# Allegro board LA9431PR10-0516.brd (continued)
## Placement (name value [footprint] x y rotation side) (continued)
UC2  -  [74AHC1G09GW_TSSOP5]  169.77 73.25 0 top
UC3  -  [TC7SH08FU_SSOP5]  173.34 58.08 90 top
UC4  -  [74AUP1G07GW_TSSOP5]  108.44 96.51 270 top
UC6  -  [74CBTLV3126BQ_DHVQFN14_2P5X3]  75.86 74.07 0 top
UC7  -  [TC7SH08FU_SSOP5]  70.61 72.93 180 top
Y1  -  [Y_X1E000021042600_4P]  184.16 77.53 270 top
Y3  -  [Y_7V25000034_4P]  260.88 79.62 270 top
Y4  -  [Y_Q13FC1350000_2P]  13.77 12.72 270 top
YC1  -  [Y_Q13FC135000040_2P]  159.67 56.2 180 bottom
YC2  -  [Y_X3G024000DC1H_4P]  139.71 92.96 270 bottom

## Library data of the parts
C1 C3 C5 C6 C9-C15 C17-C20 C22-C24 C27-C29 C34 C42 C43 C50 C54-C57 C59-C64 C66-C68 C76 C85 C87 C93-C95 C97-C99 C103 C105 C106 C108 C109 C113-C115 C119 C120 C123-C127 C129 C130 C135-C137 C139 C141 C142 C144-C148 C150 C152-C168 C170-C179 C181 C183-C186 C188-C194 C198-C204 C206-C210 C212 C214-C219 C222 C226 C227 C229 C231-C239 C241-C246 C248-C250 C252 C255-C261 C269-C279 C281-C283 C285 C287 C289 C291-C316 C319-C322 C329-C334 C337-C347 C349-C365 C367-C380 C382-C384 C386-C394 C396-C404 C406 C407 C409 C411 C412 C414-C419 C422 C425-C430 C432 C433 C440-C443 C445 C447-C449 C451 C455-C457 CC1-CC15 CC22 CC24 CC26 CC27 CC29-CC33 CC35-CC41 CC44-CC46 CC48 CC51-CC54 CC56 CC58-CC61 CC63-CC70 CC74 CC81 CC82 CC90 CC91 CC149 CC450 CD1-CD13 CD23-CD29 CD32-CD44 CD54-CD57 CD60 CD61 CE1 CE2 CE8 CE9 PC3 PC4 PC101 PC105 PC106 PC108 PC202 PC203 PC212-PC215 PC300 PC301 PC305 PC308 PC400 PC402 PC403 PC501-PC504 PC506 PC511-PC514 PC707 PC708 PC719 PC724-PC730 PC740 PC801 PC805 PC806 PC808-PC810 PC812 PC814 PC817 = C_0402
C7 C187 C251 CC47 CE7 PC5 PC10 PC102-PC104 PC107 PC200 PC201 PC205 PC302 PC303 PC401 PC404 PC706 PC711 PC712 PC716-PC718 PC731 PC732 PC734 PC736 PC737 PC741 PC742 PC807 PC900-PC929 = C_0805
C8 C16 C21 C25 C26 C52 C65 C88 C116-C118 C121 C122 C128 C131 C132 C134 C138 C140 C151 C169 C180 C182 C211 C213 C220 C221 C223-C225 C228 C230 C240 C247 C262 C284 C288 C317 C318 C323-C326 C328 C336 C348 C366 C385 C405 C408 C410 C413 C420 C431 C446 C452-C454 C458-C461 CC16-CC21 CC28 CC34 CC42 CC43 CC49 CC50 CC62 CC76 CC77 CD14-CD21 CD30 CD31 CD45-CD52 CD58 CD59 PC1 PC2 PC6-PC9 PC11 PC12 PC100 PC109-PC112 PC114 PC116-PC119 PC204 PC208 PC209 PC211 PC304 PC306 PC500 PC505 PC507-PC510 PC700 PC703-PC705 PC709 PC713-PC715 PC720-PC722 PC733 PC803 PC811 PC813 PC815 PC816 = C_0603
C253 C254 C280 C290 C444 PC307 = C_B2
C327 = C_1808
CC55 CC75 CC78 CC79 = C_1206
CC71-CC73 PC207 = C_D2
CD22 CD53 = C_D3
CMOS1 JTAG1 ME1 = SHORTPADS: User Part Number: PART#
D1 = RB751V40_SC76-2
D2 D10 D21 = BAT54CW_SOT323-3
D8 D16 D18 D33 = L30ESDL5V0C3-2_SOT23-3
D12-D14 D19 D23 D24 = RB751S40T1G_SOD523-2
D15 D17 D34 = TVWDF1004AD0_DFN9
D20 = PESD24VS2UT_SOT23-3
D30-D32 = L03ESDL5V0CC3-2_SOT23-3
D65 = RB751VM-40TE-17_SOD323-2
FD1-FD4 = FIDUCIAL_C40M80
H1-H4 H12 H13 H15-H18 ST2 = H_2P8
H5 = H_2P3
H8-H11 = H_3P4
H14 = H_2P1
JAPS1 = ACES_50506-01841-P01_18P
JDEG1 = ACES_50521-01041-P01_10P-T
JDIMM1 JDIMM2 = FOX_AS0A621-U4R6-7H_204P
JDOCK1 = JAE_WD2F144WB8-DT_144P-T
JEDP1 = ACES_50398-04071-001_40P
JFAN1 JSF1 = ACES_50277-0040N-001_4P-T
JHDMI1 = LCN_AUF05-1922S10-0019_19P-T
JHP1 = SINGA_2SJ3080-003111F_6P-T
JKBTP1 = E-T_6718K-Y16N-01L_16P-T
JLED1 = ACES_50450-0067N-P01_6P-T
JLOM1 = SANTA_130456-341_13P-T
JMDP1 = ACON_MAR2C-20K1800_20P-T
JMEDIA = E-T_6718K-Y06N-01L_6P-T
JMINI1 JMINI2 = LCN_DAN08-52216-0100_52P-T
JMINI3 = LCN_DAN08-52406-0500_52P
JNFC1 = E-T_6718K-Y15N-01L_15P-T
JRTC1 = TYCO_2-1775293-2_2P
JSD1 = ALPS_SCDADA0101_19P_NR-T
JSH1 = E-T_6718K-Y12N-01L_12P-T
JSPK1 = ACES_50209-0040N-001_4P
JTAA1 = ACES_50185-02041-001_20P-T
JUSB1 JUSB2 = SANTA_373070-1_9P-T
JUSB3 = TAITW_PUBAUE-09FLBS1FF4H0_9P-T
JUSH1 = E-T_6718K-Y20N-00L_20P-T
JXDP1 = SAMTE_BSH-030-01-L-D-A_60P
L1 L2 L4 L5 = MURAT_BLM18AG102SN1D_2P
L8 L39 L54 = MURAT_DLW21HN900SQ2L_4P
L9 L11 L12 L14 L15 L17 L18 L20 = DELTA_0402HS-9N0EJTS_2P
L10 L13 L16 L19 = MURAT_DLW21SN900HQ2L-0805_4P-S
L21 = CHILI_PBY160808T-600Y-N_2P
L22-L25 = MURAT_BLM18PG330SN1D_2P
L26 = TAIYO_CBC2012T4R7M_2P
L27-L34 = DELTA_0603CS-120EJTS_2P
L35 L36 = MURAT_BLM15AG601SN1D_2P
L37 L38 = MURAT_DLW21SN670HQ2L_4P
L40 L41 L55 L56 = MURAT_DLW21SN900HQ2L-0805_4P
L42 = CHENG_OCE2012120YZF_4P
L43 L46-L48 = MURAT_DLW21SN900SQ2L-0805_4P-S
L51 L52 = MURAT_BLM18AG221SN1D_2P
LC1-LC6 = MURAT_LQM2MPN2R2NG0L_2P
LE1 = MURAT_BLM15BB221SN1D_2P
LED1 LED5 LED6 = LED_LTW-193ZDS5_2P
LED7 = LED_LTW-295DSKS-5A_4P
PBATT1 = ALLTO_C144LS-109A9-L_9P-T
PC113 PC115 = C_V
PC735 PC738 = C_D
PD1 PD2 = TVNST52302AB0_SOT523-3
PD3 = BAS40-05W_SC70-3
PD4 PD702 = RB751V-40_SOD323-2
PD5 = DA204U_SOT323-3
PD6 = D_0603
PD701 PD815 = RB717F_SOT323-3
PD800 PD806 PD808 = PDS5100H-13_POWERDI5-3
PD807 PD810 PD811 PD813 PD814 PD816 PD818-PD821 = SDMK0340L-7-F_SOD323-2
PH500 PH501 PR1 PR2 PR7-PR15 PR17 PR18 PR100-PR102 PR104-PR107 PR114 PR201 PR204-PR207 PR209 PR211 PR300 PR302 PR303 PR305 PR307 PR308 PR400-PR403 PR500-PR516 PR521 PR523 PR527-PR529 PR535 PR537 PR540 PR703-PR707 PR711 PR713 PR714 PR722 PR726 PR727 PR729 PR730 PR732 PR734-PR740 PR742-PR744 PR746-PR749 PR751 PR801 PR802 PR804 PR807 PR808 PR810 PR813-PR819 PR822-PR824 PR826-PR830 PR836 PR837 PR839 PR840 PR844 PR846 PR848 PR849 PR851 PR856 PR858 PR864 PR869 PR870 PR874 PR875 PR894 R1-R33 R35 R36 R38-R54 R56-R60 R63-R67 R69 R70 R72 R74 R85 R91 R92 R94-R97 R99 R102 R104 R108 R120-R123 R136 R137 R139 R142 R147-R153 R155-R168 R170-R173 R176 R178 R182 R184-R187 R190 R191 R194 R195 R197 R198 R202 R205-R207 R211-R219 R222 R224-R230 R243 R244 R252-R268 R271-R282 R284 R285 R287-R289 R291-R293 R295 R296 R298-R301 R303-R305 R307 R309-R313 R317 R320-R322 R324-R331 R335 R338-R340 R342-R373 R375-R377 R380-R388 R391-R394 R397-R399 R401-R405 R408 R411 R414 R417 R421 R423 R425 R427-R436 R438-R440 R442 R445 R447 R449-R453 R460 R462-R471 R473-R475 R480 R481 R493 RC1-RC3 RC5-RC12 RC17-RC20 RC22-RC26 RC28 RC30 RC34 RC36-RC39 RC44-RC47 RC50 RC52 RC55-RC58 RC61 RC63 RC64 RC66-RC69 RC71 RC73 RC74 RC76 RC78 RC79 RC81-RC84 RC95 RC96 RC99 RC101-RC106 RC109 RC113-RC120 RC122-RC134 RC136 RC137 RC139-RC141 RC143-RC145 RC147 RC149 RC151-RC155 RC158 RC159 RC161 RC166 RC168-RC170 RC173 RC178 RC180 RC181 RC185 RC189-RC191 RC193 RC195 RC197 RC199-RC206 RC208 RC210 RC211 RC215-RC218 RC221 RC222 RC232 RC233 RC235-RC241 RC243 RC244 RC248-RC250 RC253-RC256 RC258-RC260 RC264-RC266 RC268 RC269 RC272 RC275 RC280 RC282-RC285 RC287-RC289 RC292 RC295 RD3 RE4 RE5 = R_0402
PJP1 PJP101 PJP102 PJP203 PJP204 = JUMP_43X118
PJP4-PJP25 PJP201 PJP202 PJP400-PJP402 PJP701 = JUMP_43X39
PJP100 PJP500 PJP700 = JUMP_43X118-S
PJP200 PJP300 PJP301 = JUMP_43X79
PJPDC1 = ACES_50299-00501-003_5P
PL1 PL2 PL4 = TAIYO_FBMJ4516HS720NT_2P
PL3 = MURAT_BLM15AG102SN1D_2P
PL100 = CYNTE_PCMB053T-1R0MS_2P
PL101 PL102 PL200 PL300 = CYNTE_PCMB064T-3R3MS_2P
PL500 = CYNTE_PDME064T-R36MS1R405_4P
PL501 = L_1812-1806
PL700 = CYNTE_PCMB042T-1R0MS_2P
PL701 = TOKO_FDVE1040-H-3R3M-P3_2P
PQ1 PQ801 PQ814 PQ822 PQ823 PQ829 PQ830 = FDN338P_NL_SOT23-3
PQ2 PQ816 = FDV301N_NL_SOT23-3
PQ3 Q12 = MMST3904-7-F_SOT323-3
PQ4 PQ700 = SI7121DN-T1-GE3_POWERPAK8-5
PQ6 = IMD2AT-108_SC74-6
PQ100-PQ103 PQ200 PQ201 PQ300 PQ301 = SI7326DN-T1-E3_PAK1212-8
PQ701 PQ702 = NTR4502PT1G_SOT23-3
PQ703 = NTGD4161PT1G_TSOP6
PQ704 PQ706 = SIR472DP-T1-GE3_POWERPAK8-5
PQ710 PQ712 PQ802 PQ805-PQ807 PQ812 PQ813 PQ819 PQ821 PQ824 = 2N7002DW-T-R7_SOT363-6
PQ800 PQ809 = SI4835DDY-T1-GE3_SO8
PQ810 PQ811 PQ815 = FDS6679AZ-G_SO8
PQ817 PQ818 PQ825 PQ827 PQ828 PQ831 PQ832 = RHU002N06_SOT323-3
PQ826 = FDMC6679AZ_MLP8-5
PR6 PR103 PR108 PR113 PR208 PR210 PR304 PR520 PR531 PR532 PR534 PR536 PR539 PR701 PR702 PR709 PR710 PR717-PR719 PR725 PR728 PR741 PR750 PR811 PR812 PR820 PR825 PR831-PR834 PR838 PR841 PR843 PR847 PR850 PR852-PR855 PR857 PR859-PR863 PR866 PR868 PR872 PR877 PR895 R37 R73 R75-R77 R81 R84 R88 R106 R107 R129 R131 R143-R145 R154 R169 R174 R175 R177 R179 R180 R183 R193 R196 R220 R223 R231 R241 R242 R269 R270 R297 R306 R315 R319 R332-R334 R336 R337 R341 R374 R378 R379 R400 R410 R413 R416 R418 R420 R422 R424 R426 R441 R443 R444 R472 R490-R492 RC4 RC14 RC29 RC31 RC33 RC35 RC40 RC65 RC72 RC86-RC94 RC97 RC107 RC108 RC110-RC112 RC135 RC142 RC163 RC172 RC174 RC176 RC245-RC247 RC261 RC263 RC267 RC279 RC300 RC301 RD1 RD5-RD7 RD10-RD13 = R0402_0OHM
PR16 PR708 PR835 = R_0805
PR109 PR110 PR200 PR202 PR301 PR517 PR519 PR526 PR715 PR821 RC242 RC276 = R_0603
PR111 PR112 PR203 PR306 PR522 PR724 PR745 = R_1206
PR700 PR716 = R_1206_4P-D
PRP2 RP1-RP11 = RP_0804_8P4R
PU2 = LM393DR_SO8
PU3 PU801 PU804-PU808 U20 U24 U26 U29 U30 U42 U47 UC3 UC7 = TC7SH08FU_SSOP5
PU11 = RT8207MZQW_WQFN20_3X3
PU100 = TPS51225CRUKR_QFN20_3X3
PU111 = TS5A63157DCKR_SC70-6
PU300 = TPS51218DSCR_SON10_3X3
PU400 = APL5915KAI-TRL_SO8
PU500 = TPS51622RSM_QFN32_4X4
PU501 = CSD97374CQ4M_SON8_3P5X4P5-S
PU700 = BQ24715RGRR_QFN20_3P5X3P5
PU703 = INA199A2DCKR_SC70-6
PU800 = CD3301RHHR_QFN36_6X6
Q1 Q3 = LP2301ALT1G_SOT23-3
Q2 = FDC654P-G_SSOT-6
Q4 Q7 Q9 Q29 Q121 = L2N7002WT1G_SC-70-3
Q5 Q17 Q20-Q25 Q28 Q30 Q32 Q33 Q120 Q123 Q124 QC1 = DMN66D0LDW-7_SOT363-6
Q6 Q10 Q31 = BSS138W-7-F_SOT323-3
Q11 Q13 Q14 = MMBT3904WT1G_SC70-3
Q15 Q16 Q26 = PDTA114EU_SC70-3
Q125 = SI3456DDV-T1-GE3_TSOP6
QD1 = BSS138-G_SOT23-3
R100 R101 R235-R240 R246-R251 R482-R487 = R_0402-S
R130 RC262 = R0805_0OHM
R140 R181 RC16 = R0603_0OHM
ST1 = CLIP_C5P1
SW1 = SW_SKRBAAE010_4P
T1-T7 T10-T40 T48-T89 T92 T93 T97 T98 T100 T101 T106 T107 T110 T115 T118 T121-T123 T126 T129-T132 T137-T141 = TPC12
T94 = TAIMA_IH-115-F_24P
U1 = W25Q64FVSSIQ_SO8
U2 = W25Q32FVSSIQ_SO8
U3 U18 U22 U31 U43 U45 U46 = TPS22966DPUR_SON14_2X3
U5 UC4 = 74AUP1G07GW_TSSOP5
U6 = IDTVMM2320BKG8_BGA_168P-NH
U7 = W25X10BVSNIG_SO8
U9 = APL3512ABI-TRG_SOT23-5
U11 U13 U49 = PI3C3125LEX_TSSOP14
U17 = ALC3226-CG_QFN48_7X7
U19 = PI3VDP12412ZHEX_TQFN42_9X3P5
U21 = WGI218LM-QQ89-B0_QFN48_6X6
U23 = PI3L720ZHEX_TQFN42_9X3P5
U25 = AT97SC3204-X2A14-AB_TSSOP28
U27 = OZ777FJ2LN_QFN48_6X6
U32 U35 U52 = G547I2P81U_MSOP8
U33 = PI3USB3102ZLEX_TQFN32_6X3
U36 = NX3DV221GM_XQFN10U10_2X1P55
U37 = ECE5048-LZY_DQFN132_11X11
U38 = MEC5075-LZY_DQFN132_11X11
U39 = SLG55594AVTR_TDFN8_2X2
U41 = RT9818A-44GU3_SC70-3
U48 U50 = AP2330W-7_SC59-3
UC1 = HASWELL-MCP-E-ULT_BGA_1168P-T
UC2 = 74AHC1G09GW_TSSOP5
UC6 = 74CBTLV3126BQ_DHVQFN14_2P5X3
Y1 = Y_X1E000021042600_4P
Y3 = Y_7V25000034_4P
Y4 = Y_Q13FC1350000_2P
YC1 = Y_Q13FC135000040_2P
YC2 = Y_X3G024000DC1H_4P

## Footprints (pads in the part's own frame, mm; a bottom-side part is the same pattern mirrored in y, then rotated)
2N7002DW-T-R7_SOT363-6
  oval 0.381x1.397 smd: 1(0,0) 2(0.65,0) 3(1.3,0) 4(1.3,1.725) 5(0.65,1.725) 6(0,1.725)
74AHC1G09GW_TSSOP5
  oval 0.381x1.346 smd: 1(0,0) 2(0.65,0) 3(1.3,0) 4(1.3,1.79) 5(0,1.79)
74AUP1G07GW_TSSOP5
  oval 0.381x1.346 smd: 1(0,0) 2(0.65,0) 3(1.3,0) 4(1.3,1.79) 5(0,1.79)
74CBTLV3126BQ_DHVQFN14_2P5X3
  oval 1.041x0.254 smd: 1(0,0) 7(2.95,0) 8(2.95,0.5) 14(0,0.5)
  oval 0.254x1.041 smd: 2(0.475,-0.975) 3(0.975,-0.975) 4(1.475,-0.975) 5(1.975,-0.975) 6(2.475,-0.975) 9(2.475,1.475) 10(1.975,1.475) 11(1.475,1.475) 12(0.975,1.475) 13(0.475,1.475)
  rect 1.499x0.991 smd: 15(1.475,0.25)
ACES_50185-02041-001_20P-T
  round 0.787 hole 0.787 unplated: (0.2,-1.315) (3.4,-1.315)
  oval 0.203x0.889 smd: 1(0,0) 2(0,-2.63) 3(0.4,0) 4(0.4,-2.63) 5(0.8,0) 6(0.8,-2.63) 7(1.2,0) 8(1.2,-2.63) 9(1.6,0) 10(1.6,-2.63) 11(2,0) 12(2,-2.63) 13(2.4,0) 14(2.4,-2.63) 15(2.8,0) 16(2.8,-2.63) 17(3.2,0) 18(3.2,-2.63) 19(3.6,0) 20(3.6,-2.63)
  rect 0.508x0.838 smd: 21(-0.8,-0.575) 22(-0.8,-2.055) 23(4.4,-0.575) 24(4.4,-2.055)
ACES_50209-0040N-001_4P
  oval 0.508x1.651 smd: 1(0,0) 2(0.8,0) 3(1.6,0) 4(2.4,0)
  rect 1.194x1.702 smd: 5(-1.3,-2.275) 6(3.7,-2.275)
ACES_50277-0040N-001_4P-T
  oval 0.787x1.905 smd: 1(0,0) 2(1.25,0) 3(2.5,0) 4(3.75,0)
  rect 1.295x3.353 smd: 5(-2.85,-4.925) 6(6.6,-4.925)
ACES_50299-00501-003_5P
  round 1.803 hole 1.803 unplated: (-0.2,5.2) (8.2,5.2)
  oval 0.889x2.388 smd: 1(0,0) 2(2,0) 3(4,0) 4(6,0) 5(8,0)
ACES_50398-04071-001_40P
  oval 0.254x1.295 smd: 1(0,0) 2(-0.5,0) 3(-1,0) 4(-1.5,0) 5(-2,0) 6(-2.5,0) 7(-3,0) 8(-3.5,0) 9(-4,0) 10(-4.5,0) 11(-5,0) 12(-5.5,0) 13(-6,0) 14(-6.5,0) 15(-7,0) 16(-7.5,0) 17(-8,0) 18(-8.5,0) 19(-9,0) 20(-9.5,0) 21(-10,0) 22(-10.5,0) 23(-11,0) 24(-11.5,0) 25(-12,0) 26(-12.5,0) 27(-13,0) 28(-13.5,0) 29(-14,0) 30(-14.5,0) 31(-15,0) 32(-15.5,0) 33(-16,0) 34(-16.5,0) 35(-17,0) 36(-17.5,0) 37(-18,0) 38(-18.5,0) 39(-19,0) 40(-19.5,0)
  rect 1.194x3.2 smd: 41(-21.9,1.95) 45(2.4,1.95)
  rect 2.311x1.295 smd: 42(-18.65,3.9) 43(-9.75,3.9) 44(-0.85,3.9)
ACES_50450-0067N-P01_6P-T
  oval 0.508x1.295 smd: 1(0,0) 2(0.8,0) 3(1.6,0) 4(2.4,0) 5(3.2,0) 6(4,0)
  rect 1.194x1.702 smd: 7(-1.3,1.3) 8(5.3,1.3)
ACES_50506-01841-P01_18P
  oval 0.305x0.889 smd: 1(0,0) 2(0.5,0) 3(1,0) 4(1.5,0) 5(2,0) 6(2.5,0) 7(3,0) 8(3.5,0) 9(4,0) 10(4.5,0) 11(5,0) 12(5.5,0) 13(6,0) 14(6.5,0) 15(7,0) 16(7.5,0) 17(8,0) 18(8.5,0)
  rect 0.991x2.007 smd: 19(-2.1,-3.05) 20(10.6,-3.05)
ACES_50521-01041-P01_10P-T
  oval 0.305x0.787 smd: 1(0,0) 2(-0.5,0) 3(-1,0) 4(-1.5,0) 5(-2,0) 6(-2.5,0) 7(-3,0) 8(-3.5,0) 9(-4,0) 10(-4.5,0)
  rect 0.406x0.787 smd: 11(-5.5,-2.5) 12(1,-2.5)
ACON_MAR2C-20K1800_20P-T
  round 1.194 hole 1.194 unplated: (-6.95,-0.5) (1.55,-0.5)
  round 0.813 hole 0.508: 1(0,0) 3(-0.6,-1.2) 5(-1.1,0) 7(-1.7,-1.2) 9(-2.2,0) 11(-3.2,0) 13(-3.7,-1.2) 15(-4.3,0) 17(-4.8,-1.2) 19(-5.4,0)
  oval 0.406x1.88 smd: 2(0,-2.995) 4(-0.6,-2.995) 6(-1.2,-2.995) 8(-1.8,-2.995) 10(-2.4,-2.995) 12(-3,-2.995) 14(-3.6,-2.995) 16(-4.2,-2.995) 18(-4.8,-2.995) 20(-5.4,-2.995)
  oval 1.194x2.261 hole 0.711x1.753: 21(-8.2,2.96) 22(-8.2,-2.04) 23(2.8,2.96) 24(2.8,-2.04)
ALC3226-CG_QFN48_7X7
  oval 0.254x0.889 smd: 1(0,0) 2(0.5,0) 3(1,0) 4(1.5,0) 5(2,0) 6(2.5,0) 7(3,0) 8(3.5,0) 9(4,0) 10(4.5,0) 11(5,0) 12(5.5,0) 25(5.5,7.1) 26(5,7.1) 27(4.5,7.1) 28(4,7.1) 29(3.5,7.1) 30(3,7.1) 31(2.5,7.1) 32(2,7.1) 33(1.5,7.1) 34(1,7.1) 35(0.5,7.1) 36(0,7.1)
  oval 0.889x0.254 smd: 13(6.3,0.8) 14(6.3,1.3) 15(6.3,1.8) 16(6.3,2.3) 17(6.3,2.8) 18(6.3,3.3) 19(6.3,3.8) 20(6.3,4.3) 21(6.3,4.8) 22(6.3,5.3) 23(6.3,5.8) 24(6.3,6.3) 37(-0.8,6.3) 38(-0.8,5.8) 39(-0.8,5.3) 40(-0.8,4.8) 41(-0.8,4.3) 42(-0.8,3.8) 43(-0.8,3.3) 44(-0.8,2.8) 45(-0.8,2.3) 46(-0.8,1.8) 47(-0.8,1.3) 48(-0.8,0.8)
  rect 5.512x5.512 smd: 49(2.75,3.55)
ALLTO_C144LS-109A9-L_9P-T
  round 1.803 hole 1.194: 1(0,0) 2(2,0) 3(4,0) 4(6,0) 5(8,0) 6(10,0) 7(12,0) 8(14,0) 9(16,0)
  oval 1.6x3.404 hole 0.991x2.794: 10(19.125,0.25) 11(-3.125,0.25)
ALPS_SCDADA0101_19P_NR-T
  round 0.889 hole 0.889 unplated: (-7.075,-28.875) (13.425,-1.775)
  oval 0.787x1.549 smd: 1(0,0) 2(1.4,0) 3(2.8,0) 4(4.2,0) 5(7.1,0) 6(9.9,0) 7(11.3,0) 8(12.7,0) 9(-1.4,0) 18(8.5,0) 19(14.1,0)
  oval 1.346x0.787 smd: 10(-9.2,-22.925) 11(-9.2,-24.025) 12(-9.2,-25.125) 13(-9.2,-26.225) 14(20.05,-26.225) 15(20.05,-25.125) 16(20.05,-24.025) 17(20.05,-22.925)
  rect 1.397x1.448 smd: 20(17.2,0.65) 21(5.65,0.65) 22(-6.35,0.65)
  rect 1.448x1.397 smd: 23(19.525,-6.525) 24(-8.675,-6.525) 25(19.525,-20.625) 26(-8.675,-18.775)
AP2330W-7_SC59-3
  oval 0.787x0.991 smd: 1(0,0) 2(-0.95,-2.4) 3(0.95,-2.4)
APL3512ABI-TRG_SOT23-5
  oval 0.61x1.041 smd: 1(0,0) 2(0.95,0) 3(1.9,0) 4(1.9,2.7) 5(0,2.7)
APL5915KAI-TRL_SO8
  oval 0.635x1.854 smd: 1(0,0) 2(1.27,0) 3(2.54,0) 4(3.81,0) 5(3.81,5.165) 6(2.54,5.165) 7(1.27,5.165) 8(0,5.165)
  rect 2.997x2.591 smd: 9(1.905,2.582)
AT97SC3204-X2A14-AB_TSSOP28
  oval 0.381x1.626 smd: 1(0,0) 2(0.65,0) 3(1.3,0) 4(1.95,0) 5(2.6,0) 6(3.25,0) 7(3.9,0) 8(4.55,0) 9(5.2,0) 10(5.85,0) 11(6.5,0) 12(7.15,0) 13(7.8,0) 14(8.45,0) 15(8.45,5.8) 16(7.8,5.8) 17(7.15,5.8) 18(6.5,5.8) 19(5.85,5.8) 20(5.2,5.8) 21(4.55,5.8) 22(3.9,5.8) 23(3.25,5.8) 24(2.6,5.8) 25(1.95,5.8) 26(1.3,5.8) 27(0.65,5.8) 28(0,5.8)
BAS40-05W_SC70-3
  oval 0.508x0.559 smd: 1(0,0) 2(-0.65,-1.85) 3(0.65,-1.85)
BAT54CW_SOT323-3
  oval 0.66x0.864 smd: 1(0,0) 2(-0.65,-1.85) 3(0.65,-1.85)
BQ24715RGRR_QFN20_3P5X3P5
  oval 0.254x1.041 smd: 1(0,0) 2(0.5,0) 3(1,0) 4(1.5,0) 5(2,0) 11(2,3.45) 12(1.5,3.45) 13(1,3.45) 14(0.5,3.45) 15(0,3.45)
  oval 1.041x0.254 smd: 6(2.725,0.725) 7(2.725,1.225) 8(2.725,1.725) 9(2.725,2.225) 10(2.725,2.725) 16(-0.725,2.725) 17(-0.725,2.225) 18(-0.725,1.725) 19(-0.725,1.225) 20(-0.725,0.725)
  rect 2.057x2.057 smd: 21(1,1.725)
BSS138-G_SOT23-3
  oval 1.016x1.524 smd: 1(0,0) 2(0.965,2.083) 3(-0.965,2.083)
BSS138W-7-F_SOT323-3
  oval 0.711x0.889 smd: 1(0,0) 2(-0.65,-1.9) 3(0.65,-1.9)
C_0402
  rect 0.508x0.559 smd: 1(0,0) 2(0.914,0)
C_0603
  rect 0.635x0.889 smd: 1(0,0) 2(1.397,0)
C_0805
  rect 0.813x1.397 smd: 1(0,0) 2(1.702,0)
C_1206
  rect 1.016x1.651 smd: 1(0,0) 2(2.667,0)
C_1808
  rect 1.041x2.311 smd: 1(0,0) 2(4.35,0)
C_B2
  rect 1.346x2.692 smd: 1(0,0) 2(-2.75,0)
C_D
  rect 2.388x2.896 smd: 1(0,0) 2(6.1,0)
C_D2
  rect 2.388x2.794 smd: 1(0,0) 2(6.4,0)
C_D3
  rect 2.388x2.794 smd: 1(0,0) 2(6.4,0)
C_V
  rect 2.388x2.896 smd: 1(0,0) 2(6.1,0)
CD3301RHHR_QFN36_6X6
  oval 0.254x1.194 smd: 1(0,0) 2(0.5,0) 3(1,0) 4(1.5,0) 5(2,0) 6(2.5,0) 7(3,0) 8(3.5,0) 9(4,0) 19(4,5.8) 20(3.5,5.8) 21(3,5.8) 22(2.5,5.8) 23(2,5.8) 24(1.5,5.8) 25(1,5.8) 26(0.5,5.8) 27(0,5.8)
  oval 1.194x0.254 smd: 10(4.9,0.9) 11(4.9,1.4) 12(4.9,1.9) 13(4.9,2.4) 14(4.9,2.9) 15(4.9,3.4) 16(4.9,3.9) 17(4.9,4.4) 18(4.9,4.9) 28(-0.9,4.9) 29(-0.9,4.4) 30(-0.9,3.9) 31(-0.9,3.4) 32(-0.9,2.9) 33(-0.9,2.4) 34(-0.9,1.9) 35(-0.9,1.4) 36(-0.9,0.9)
  rect 4.089x4.089 smd: 37(2,2.9)
CHENG_OCE2012120YZF_4P
  rect 0.889x0.787 smd: 1(0,0) 2(1.7,0) 3(1.7,1.2) 4(0,1.2)
CHILI_PBY160808T-600Y-N_2P
  rect 0.559x1.041 smd: 1(0,0) 2(1.3,0)
CLIP_C5P1
  round 5.105 smd: 1(0,0)
CSD97374CQ4M_SON8_3P5X4P5-S
  oval 0.203x0.914 smd: 1(0,0) 2(0.4,0) 3(0.8,0) 6(0.8,3.505) 7(0.4,3.505) 8(0,3.505)
  custom 0.225x0.225 smd: 4(2.2,0.265) 5(2.2,3.24)
  rect 4.039x2.21 smd: 9(1.6,1.752)
CYNTE_PCMB042T-1R0MS_2P
  rect 1.499x2.489 smd: 1(0,0) 2(3.7,0)
CYNTE_PCMB053T-1R0MS_2P
  rect 1.905x2.794 smd: 1(0,0) 2(4.1,0)
CYNTE_PCMB064T-3R3MS_2P
  rect 2.362x3.505 smd: 1(0,0) 2(6.05,0)
CYNTE_PDME064T-R36MS1R405_4P
  custom 0.686x0.686 smd: 1(0,0) 4(8.509,0)
  rect 2.362x0.508 smd: 2(1.448,0) 3(7.061,0)
D_0603
  oval 0.864x1.219 smd: 1(-0.711,0) 2(0.711,0)
DA204U_SOT323-3
  oval 0.813x0.914 smd: 1(0,0) 2(0.65,1.6) 3(-0.65,1.6)
DELTA_0402HS-9N0EJTS_2P
  rect 0.508x0.66 smd: 1(0,0) 2(0.96,0)
DELTA_0603CS-120EJTS_2P
  rect 0.635x1.016 smd: 1(0,0) 2(1.28,0)
DMN66D0LDW-7_SOT363-6
  oval 0.432x0.61 smd: 1(0,0) 2(0.65,0) 3(1.3,0) 4(1.3,1.9) 5(0.65,1.9) 6(0,1.9)
E-T_6718K-Y06N-01L_6P-T
  oval 0.305x0.787 smd: 1(0,0) 2(0.5,0) 3(1,0) 4(1.5,0) 5(2,0) 6(2.5,0)
  rect 0.406x0.787 smd: 7(-1,-2.5) 8(3.5,-2.5)
E-T_6718K-Y12N-01L_12P-T
  oval 0.305x0.787 smd: 1(0,0) 2(0.5,0) 3(1,0) 4(1.5,0) 5(2,0) 6(2.5,0) 7(3,0) 8(3.5,0) 9(4,0) 10(4.5,0) 11(5,0) 12(5.5,0)
  rect 0.406x0.787 smd: 13(-1,-2.5) 14(6.5,-2.5)
E-T_6718K-Y15N-01L_15P-T
  oval 0.305x0.787 smd: 1(0,0) 2(0.5,0) 3(1,0) 4(1.5,0) 5(2,0) 6(2.5,0) 7(3,0) 8(3.5,0) 9(4,0) 10(4.5,0) 11(5,0) 12(5.5,0) 13(6,0) 14(6.5,0) 15(7,0)
  rect 0.406x0.787 smd: 16(-1,-2.5) 17(8,-2.5)
E-T_6718K-Y16N-01L_16P-T
  oval 0.305x0.787 smd: 1(0,0) 2(0.5,0) 3(1,0) 4(1.5,0) 5(2,0) 6(2.5,0) 7(3,0) 8(3.5,0) 9(4,0) 10(4.5,0) 11(5,0) 12(5.5,0) 13(6,0) 14(6.5,0) 15(7,0) 16(7.5,0)
  rect 0.406x0.787 smd: 17(-1,-2.5) 18(8.5,-2.5)
E-T_6718K-Y20N-00L_20P-T
  oval 0.305x0.787 smd: 1(0,0) 2(0.5,0) 3(1,0) 4(1.5,0) 5(2,0) 6(2.5,0) 7(3,0) 8(3.5,0) 9(4,0) 10(4.5,0) 11(5,0) 12(5.5,0) 13(6,0) 14(6.5,0) 15(7,0) 16(7.5,0) 17(8,0) 18(8.5,0) 19(9,0) 20(9.5,0)
  rect 0.406x0.787 smd: 21(-1,-2.5) 22(10.5,-2.5)
ECE5048-LZY_DQFN132_11X11
  oval 0.279x0.737 smd: A1(0,0) A2(0.5,0) A3(1,0) A4(1.5,0) A5(2,0) A6(2.5,0) A7(3,0) A8(3.5,0) A9(4,0) A10(4.5,0) A11(5,0) A12(5.5,0) A13(6,0) A14(6.5,0) A15(7,0) A16(7.5,0) A33(7.5,10.9) A34(7,10.9) A35(6.5,10.9) A36(6,10.9) A37(5.5,10.9) A38(5,10.9) A39(4.5,10.9) A40(4,10.9) A41(3.5,10.9) A42(3,10.9) A43(2.5,10.9) A44(2,10.9) A45(1.5,10.9) A46(1,10.9) A47(0.5,10.9) A48(0,10.9)
  oval 0.737x0.279 smd: A17(9.2,1.7) A18(9.2,2.2) A19(9.2,2.7) A20(9.2,3.2) A21(9.2,3.7) A22(9.2,4.2) A23(9.2,4.7) A24(9.2,5.2) A25(9.2,5.7) A26(9.2,6.2) A27(9.2,6.7) A28(9.2,7.2) A29(9.2,7.7) A30(9.2,8.2) A31(9.2,8.7) A32(9.2,9.2) A49(-1.7,9.2) A50(-1.7,8.7) A51(-1.7,8.2) A52(-1.7,7.7) A53(-1.7,7.2) A54(-1.7,6.7) A55(-1.7,6.2) A56(-1.7,5.7) A57(-1.7,5.2) A58(-1.7,4.7) A59(-1.7,4.2) A60(-1.7,3.7) A61(-1.7,3.2) A62(-1.7,2.7) A63(-1.7,2.2) A64(-1.7,1.7)
  oval 0.318x0.61 smd: B1(-0.25,0.855) B2(0.25,0.855) B3(0.75,0.855) B4(1.25,0.855) B5(1.75,0.855) B6(2.25,0.855) B7(2.75,0.855) B8(3.25,0.855) B9(3.75,0.855) B10(4.25,0.855) B11(4.75,0.855) B12(5.25,0.855) B13(5.75,0.855) B14(6.25,0.855) B15(6.75,0.855) B16(7.25,0.855) B17(7.75,0.855) B35(7.75,10.045) B36(7.25,10.045) B37(6.75,10.045) B38(6.25,10.045) B39(5.75,10.045) B40(5.25,10.045) B41(4.75,10.045) B42(4.25,10.045) B43(3.75,10.045) B44(3.25,10.045) B45(2.75,10.045) B46(2.25,10.045) B47(1.75,10.045) B48(1.25,10.045) B49(0.75,10.045) B50(0.25,10.045) B51(-0.25,10.045)
  oval 0.61x0.318 smd: B18(8.345,1.45) B19(8.345,1.95) B20(8.345,2.45) B21(8.345,2.95) B22(8.345,3.45) B23(8.345,3.95) B24(8.345,4.45) B25(8.345,4.95) B26(8.345,5.45) B27(8.345,5.95) B28(8.345,6.45) B29(8.345,6.95) B30(8.345,7.45) B31(8.345,7.95) B32(8.345,8.45) B33(8.345,8.95) B34(8.345,9.45) B52(-0.845,9.45) B53(-0.845,8.95) B54(-0.845,8.45) B55(-0.845,7.95) B56(-0.845,7.45) B57(-0.845,6.95) B58(-0.845,6.45) B59(-0.845,5.95) B60(-0.845,5.45) B61(-0.845,4.95) B62(-0.845,4.45) B63(-0.845,3.95) B64(-0.845,3.45) B65(-0.845,2.95) B66(-0.845,2.45) B67(-0.845,1.95) B68(-0.845,1.45)
  rect 5.105x5.105 smd: C1(3.75,5.45)
FDC654P-G_SSOT-6
  oval 0.711x0.991 smd: 1(0,0) 2(0.95,0) 3(1.9,0) 4(1.9,2.6) 5(0.95,2.6) 6(0,2.6)
FDMC6679AZ_MLP8-5
  oval 0.432x0.711 smd: 1(0,0) 2(0.65,0) 3(1.3,0) 4(1.95,0)
  custom 0.537x0.537 smd: 5(0.975,2.075)
FDN338P_NL_SOT23-3
  oval 1.016x1.524 smd: 1(0,0) 2(0.965,2.083) 3(-0.965,2.083)
FDS6679AZ-G_SO8
  oval 0.635x1.676 smd: 1(0,0) 2(1.27,0) 3(2.54,0) 4(3.81,0) 5(3.81,5.35) 6(2.54,5.35) 7(1.27,5.35) 8(0,5.35)
FDV301N_NL_SOT23-3
  oval 1.016x1.524 smd: 1(0,0) 2(0.965,2.083) 3(-0.965,2.083)
FIDUCIAL_C40M80
  round 1.016 smd: 1(0,0)
FOX_AS0A621-U4R6-7H_204P
  round 1.092 hole 1.092 unplated: (-65.05,-4.1)
  round 1.6 hole 1.6 unplated: (1.75,-4.1)
  oval 0.356x2.007 smd: 1(0,0) 2(-0.3,-8.2) 3(-0.6,0) 4(-0.9,-8.2) 5(-1.2,0) 6(-1.5,-8.2) 7(-1.8,0) 8(-2.1,-8.2) 9(-2.4,0) 10(-2.7,-8.2) 11(-3,0) 12(-3.3,-8.2) 13(-3.6,0) 14(-3.9,-8.2) 15(-4.2,0) 16(-4.5,-8.2) 17(-4.8,0) 18(-5.1,-8.2) 19(-5.4,0) 20(-5.7,-8.2) 21(-6,0) 22(-6.3,-8.2) 23(-6.6,0) 24(-6.9,-8.2) 25(-7.2,0) 26(-7.5,-8.2) 27(-7.8,0) 28(-8.1,-8.2) 29(-8.4,0) 30(-8.7,-8.2) 31(-9,0) 32(-9.3,-8.2) 33(-9.6,0) 34(-9.9,-8.2) 35(-10.2,0) 36(-10.5,-8.2) 37(-10.8,0) 38(-11.1,-8.2) 39(-11.4,0) 40(-11.7,-8.2) 41(-12,0) 42(-12.3,-8.2) 43(-12.6,0) 44(-12.9,-8.2) 45(-13.2,0) 46(-13.5,-8.2) 47(-13.8,0) 48(-14.1,-8.2) 49(-14.4,0) 50(-14.7,-8.2) 51(-15,0) 52(-15.3,-8.2) 53(-15.6,0) 54(-15.9,-8.2) 55(-16.2,0) 56(-16.5,-8.2) 57(-16.8,0) 58(-17.1,-8.2) 59(-17.4,0) 60(-17.7,-8.2) 61(-18,0) 62(-18.3,-8.2) 63(-18.6,0) 64(-18.9,-8.2) 65(-19.2,0) 66(-19.5,-8.2) 67(-19.8,0) 68(-20.1,-8.2) 69(-20.4,0) 70(-20.7,-8.2) 71(-21,0) 72(-21.3,-8.2) 73(-24,0) 74(-24.3,-8.2) 75(-24.6,0) 76(-24.9,-8.2) 77(-25.2,0) 78(-25.5,-8.2) 79(-25.8,0) 80(-26.1,-8.2) 81(-26.4,0) 82(-26.7,-8.2) 83(-27,0) 84(-27.3,-8.2) 85(-27.6,0) 86(-27.9,-8.2) 87(-28.2,0) 88(-28.5,-8.2) 89(-28.8,0) 90(-29.1,-8.2) 91(-29.4,0) 92(-29.7,-8.2) 93(-30,0) 94(-30.3,-8.2) 95(-30.6,0) 96(-30.9,-8.2) 97(-31.2,0) 98(-31.5,-8.2) 99(-31.8,0) 100(-32.1,-8.2) 101(-32.4,0) 102(-32.7,-8.2) 103(-33,0) 104(-33.3,-8.2) 105(-33.6,0) 106(-33.9,-8.2) 107(-34.2,0) 108(-34.5,-8.2) 109(-34.8,0) 110(-35.1,-8.2) 111(-35.4,0) 112(-35.7,-8.2) 113(-36,0) 114(-36.3,-8.2) 115(-36.6,0) 116(-36.9,-8.2) 117(-37.2,0) 118(-37.5,-8.2) 119(-37.8,0) 120(-38.1,-8.2) 121(-38.4,0) 122(-38.7,-8.2) 123(-39,0) 124(-39.3,-8.2) 125(-39.6,0) 126(-39.9,-8.2) 127(-40.2,0) 128(-40.5,-8.2) 129(-40.8,0) 130(-41.1,-8.2) 131(-41.4,0) 132(-41.7,-8.2) 133(-42,0) 134(-42.3,-8.2) 135(-42.6,0) 136(-42.9,-8.2) 137(-43.2,0) 138(-43.5,-8.2) 139(-43.8,0) 140(-44.1,-8.2) 141(-44.4,0) 142(-44.7,-8.2) 143(-45,0) 144(-45.3,-8.2) 145(-45.6,0) 146(-45.9,-8.2) 147(-46.2,0) 148(-46.5,-8.2) 149(-46.8,0) 150(-47.1,-8.2) 151(-47.4,0) 152(-47.7,-8.2) 153(-48,0) 154(-48.3,-8.2) 155(-48.6,0) 156(-48.9,-8.2) 157(-49.2,0) 158(-49.5,-8.2) 159(-49.8,0) 160(-50.1,-8.2) 161(-50.4,0) 162(-50.7,-8.2) 163(-51,0) 164(-51.3,-8.2) 165(-51.6,0) 166(-51.9,-8.2) 167(-52.2,0) 168(-52.5,-8.2) 169(-52.8,0) 170(-53.1,-8.2) 171(-53.4,0) 172(-53.7,-8.2) 173(-54,0) 174(-54.3,-8.2) 175(-54.6,0) 176(-54.9,-8.2) 177(-55.2,0) 178(-55.5,-8.2) 179(-55.8,0) 180(-56.1,-8.2) 181(-56.4,0) 182(-56.7,-8.2) 183(-57,0) 184(-57.3,-8.2) 185(-57.6,0) 186(-57.9,-8.2) 187(-58.2,0) 188(-58.5,-8.2) 189(-58.8,0) 190(-59.1,-8.2) 191(-59.4,0) 192(-59.7,-8.2) 193(-60,0) 194(-60.3,-8.2) 195(-60.6,0) 196(-60.9,-8.2) 197(-61.2,0) 198(-61.5,-8.2) 199(-61.8,0) 200(-62.1,-8.2) 201(-62.4,0) 202(-62.7,-8.2) 203(-63,0) 204(-63.3,-8.2)
  rect 3.505x4.597 smd: 205(-64.45,7.9) 206(1.15,7.9)
G547I2P81U_MSOP8
  oval 0.381x1.549 smd: 1(0,0) 2(0.65,0) 3(1.3,0) 4(1.95,0) 5(1.95,4.37) 6(1.3,4.37) 7(0.65,4.37) 8(0,4.37)
H_2P1
  round 2.616 hole 2.108: 1(0,0)
H_2P3
  round 2.819 hole 2.311: 1(0,0)
H_2P8
  round 3.302 hole 2.794: 1(0,0)
H_3P4
  round 3.912 hole 3.404: 1(0,0)
HASWELL-MCP-E-ULT_BGA_1168P-T
  round 0.508 smd: A3(-1.137,0) A62(-38.036,0) AW1(0,22.042) AW63(-38.628,22.057) AY2(-0.543,22.628) AY62(-38.062,22.628) B2(-0.508,0.508) B63(-38.628,0.592) C1(0,1.137)
  round 0.381 smd: A4(-1.894,0) A5(-2.554,0) A6(-3.75,0) A59(-35.9,0) A60(-36.726,0) A61(-37.386,0) AA9(-5.032,11.576) AA21(-11.688,11.489) AA23(-13.115,11.489) AA58(-35.377,11.33) AB10(-5.476,12.053) AB20(-11.18,11.896) AB21(-11.688,12.302) AB22(-12.607,11.896) AB23(-13.115,12.302) AB57(-35.057,11.98) AC9(-5.032,12.529) AC20(-11.18,12.709) AC22(-12.607,12.709) AC58(-35.377,12.63) AD10(-5.476,13.005) AD21(-11.688,13.115) AD23(-13.115,13.115) AD57(-35.057,13.28) AE9(-5.032,13.481) AE10(-5.476,13.958) AE20(-11.18,13.521) AE21(-11.688,13.928) AE22(-12.607,13.521) AE23(-13.115,13.928) AE58(-35.377,13.931) AF9(-5.032,14.434) AF11(-6.059,14.282) AF12(-6.872,14.282) AF14(-7.685,14.282) AF15(-8.497,14.282) AF17(-9.31,14.282) AF18(-10.123,14.282) AF20(-10.936,14.282) AF22(-12.607,14.334) AG10(-5.653,14.79) AG11(-6.465,14.79) AG13(-7.278,14.79) AG14(-8.091,14.79) AG16(-8.904,14.79) AG17(-9.717,14.79) AG19(-10.529,14.79) AG20(-11.342,14.79) AG23(-13.115,14.741) AG57(-35.057,14.581) AG58(-35.692,15.009) AH22(-12.607,15.147) AH24(-13.92,15.289) AH26(-15.22,15.289) AH28(-16.521,15.289) AH30(-17.821,15.289) AH32(-19.122,15.289) AH34(-20.422,15.289) AH36(-21.723,15.289) AH38(-23.023,15.289) AH40(-24.324,15.289) AH42(-25.624,15.289) AH44(-26.925,15.289) AH46(-28.225,15.289) AH49(-29.526,15.289) AH51(-30.826,15.289) AH53(-32.127,15.289) AH55(-33.427,15.289) AH57(-34.728,15.289) AJ23(-13.115,15.553) AJ25(-14.57,15.614) AJ27(-15.871,15.614) AJ29(-17.171,15.614) AJ31(-18.472,15.614) AJ33(-19.772,15.614) AJ35(-21.073,15.614) AJ37(-22.373,15.614) AJ39(-23.674,15.614) AJ41(-24.974,15.614) AJ43(-26.275,15.614) AJ45(-27.575,15.614) AJ47(-28.875,15.614) AJ50(-30.176,15.614) AJ52(-31.476,15.614) AJ54(-32.777,15.614) AJ56(-34.077,15.614) AJ58(-35.378,15.614) AT1(0,19.997) AT63(-38.628,19.848) AU1(0,20.657) AU63(-38.628,20.673) AV1(0,21.318) AV2(-0.66,21.308) AV62(-37.978,21.318) AV63(-38.628,21.333) AW2(-0.66,21.968) AW3(-1.321,21.968) AW61(-37.328,21.978) AW62(-37.978,21.978) AY3(-1.267,22.628) AY4(-1.928,22.628) AY5(-2.588,22.628) AY59(-36.088,22.628) AY60(-36.748,22.628) AY61(-37.409,22.628) B3(-1.259,0.65) B61(-37.315,0.66) B62(-37.978,0.724) C2(-0.65,1.259) C62(-37.978,1.384) C63(-38.628,1.316) D1(0,1.861) D63(-38.628,1.976) E1(0,2.522) E23(-13.333,2.601) E25(-14.714,2.601) E27(-15.84,2.601) E29(-17.221,2.601) E31(-18.348,2.601) E33(-19.729,2.601) E35(-20.855,2.601) E37(-22.236,2.601) E39(-23.363,2.601) E41(-24.744,2.601) E43(-25.87,2.601) E45(-27.251,2.601) E47(-28.378,2.601) E49(-29.759,2.601) E51(-30.885,2.601) E53(-32.266,2.601) E55(-33.393,2.601) E57(-34.774,2.601) E63(-38.628,2.647) F1(0,3.436) F22(-12.717,3.058) F24(-14.023,3.126) F26(-15.277,3.126) F28(-16.531,3.126) F30(-17.785,3.126) F32(-19.038,3.126) F34(-20.292,3.126) F36(-21.546,3.126) F38(-22.8,3.126) F40(-24.053,3.126) F42(-25.307,3.126) F44(-26.561,3.126) F46(-27.815,3.126) F48(-29.068,3.126) F50(-30.322,3.126) F52(-31.576,3.126) F54(-32.83,3.126) F56(-34.083,3.126) F58(-35.377,3.126) G22(-12.607,3.768) G23(-13.333,3.451) G25(-14.714,3.451) G27(-15.84,3.451) G29(-17.221,3.451) G31(-18.348,3.451) G33(-19.729,3.451) G35(-20.855,3.451) G37(-22.236,3.451) G39(-23.363,3.451) G41(-24.744,3.451) G43(-25.87,3.451) G45(-27.251,3.451) G47(-28.378,3.451) G49(-29.759,3.451) G51(-30.885,3.451) G53(-32.266,3.451) G55(-33.393,3.451) G57(-34.774,3.451) H22(-12.607,4.581) H23(-13.115,4.174) H57(-35.057,4.101) J22(-12.607,5.393) J23(-13.115,4.987) J58(-35.377,4.827) K9(-5.032,5.861) K10(-5.935,5.7) K12(-6.888,5.7) K14(-7.84,5.7) K16(-8.793,5.7) K18(-9.745,5.7) K19(-10.698,5.7) K21(-11.65,5.7) K23(-13.115,5.8) K57(-35.057,5.478) L10(-5.476,6.338) L11(-6.412,6.144) L13(-7.364,6.144) L15(-8.317,6.144) L17(-9.269,6.144) L18(-10.222,6.144) L20(-11.18,6.206) L22(-12.607,6.206) L58(-35.377,6.128) M9(-5.032,6.814) M20(-11.18,7.019) M21(-11.688,6.613) M22(-12.607,7.019) M23(-13.115,6.613) M57(-35.057,6.778) N10(-5.476,7.29) N21(-11.688,7.425) N23(-13.115,7.425) N58(-35.377,7.428) P9(-5.032,7.766) P20(-11.18,7.832) P22(-12.607,7.832) P57(-35.057,8.078) R10(-5.476,8.243) R20(-11.18,8.645) R21(-11.688,8.238) R22(-12.607,8.645) R23(-13.115,8.238) T9(-5.032,8.719) T21(-11.688,9.051) T23(-13.115,9.051) T58(-35.377,8.729) U9(-5.032,9.671) U10(-5.476,9.195) U20(-11.18,9.457) U22(-12.607,9.457) U57(-35.057,9.379) V10(-5.476,10.148) V21(-11.688,9.864) V23(-13.115,9.864) V58(-35.377,10.029) W9(-5.032,10.624) W20(-11.18,10.27) W21(-11.688,10.677) W22(-12.607,10.27) W23(-13.115,10.677) W57(-35.057,10.679) Y10(-5.476,11.1) Y20(-11.18,11.083) Y22(-12.607,11.083)
  round 0.305 smd: A8(-4.538,0) A9(-5.452,0) A11(-6.367,0) A12(-7.116,0) A14(-8.03,0) A15(-8.945,0) A17(-9.694,0) A18(-10.608,0) A20(-11.523,0) A21(-12.272,0) A23(-13.186,0) A24(-14.023,0.325) A25(-14.714,0) A27(-15.84,0) A28(-16.531,0.325) A29(-17.221,0) A31(-18.348,0) A32(-19.038,0.325) A33(-19.729,0) A35(-20.855,0) A36(-21.546,0.325) A37(-22.236,0) A39(-23.363,0) A40(-24.053,0.325) A41(-24.744,0) A43(-25.87,0) A44(-26.561,0.325) A45(-27.251,0) A47(-28.378,0) A48(-29.068,0.325) A49(-29.759,0) A51(-30.885,0) A52(-31.576,0.325) A53(-32.266,0) A55(-33.393,0) A56(-34.083,0.325) A57(-34.774,0) AA1(0,11.717) AA2(-0.65,11.717) AA3(-1.3,11.678) AA4(-1.951,11.678) AA59(-36.027,11.638) AA60(-36.678,11.638) AA61(-37.328,11.638) AA62(-37.978,11.676) AA63(-38.628,11.676) AB5(-2.637,12.053) AB6(-3.287,12.053) AB7(-3.937,12.053) AB8(-4.587,12.053) AC1(0,12.466) AC2(-0.65,12.466) AC3(-1.3,12.504) AC4(-1.951,12.504) AC59(-36.027,12.464) AC60(-36.678,12.464) AC61(-37.328,12.464) AC62(-37.978,12.426) AC63(-38.628,12.426) AD1(0,13.215) AD2(-0.65,13.215) AD3(-1.3,13.177) AD4(-1.951,13.177) AD5(-2.637,13.005) AD6(-3.287,13.005) AD7(-3.937,13.005) AD8(-4.587,13.005) AD59(-36.027,13.137) AD60(-36.678,13.137) AD61(-37.328,13.137) AD62(-37.978,13.175) AD63(-38.628,13.175) AE5(-2.637,13.958) AE6(-3.287,13.958) AE7(-3.937,13.958) AE8(-4.587,13.958) AE59(-36.027,13.962) AE60(-36.678,13.962) AE61(-37.328,13.962) AE62(-37.978,13.924) AE63(-38.628,13.924) AF1(0,13.964) AF2(-0.65,13.964) AF3(-1.3,14.003) AF4(-1.951,14.003) AG1(0,14.714) AG2(-0.65,14.714) AG3(-1.3,14.676) AG4(-1.951,14.676) AG5(-2.637,14.91) AG6(-3.287,14.91) AG7(-3.937,14.91) AG8(-4.587,14.91) AG21(-11.955,15.122) AG60(-36.352,14.602) AG61(-37.003,14.602) AG62(-37.653,14.602) AG63(-38.303,14.602) AH1(0,15.463) AH2(-0.65,15.463) AH3(-1.3,15.501) AH4(-1.951,15.501) AH10(-5.653,15.476) AH11(-6.465,15.476) AH13(-7.278,15.476) AH14(-8.091,15.476) AH16(-8.904,15.476) AH17(-9.717,15.476) AH19(-10.529,15.476) AH20(-11.342,15.476) AH60(-36.678,15.278) AH61(-37.328,15.278) AH62(-37.978,15.278) AH63(-38.628,15.278) AJ5(-2.637,15.863) AJ6(-3.287,15.863) AJ7(-3.937,15.863) AJ8(-4.587,15.863) AJ10(-5.653,16.126) AJ11(-6.465,16.126) AJ13(-7.278,16.126) AJ14(-8.091,16.126) AJ60(-36.352,15.954) AJ61(-37.003,15.954) AJ62(-37.653,15.954) AJ63(-38.303,15.954) AK1(0,16.212) AK2(-0.65,16.212) AK3(-1.3,16.174) AK4(-1.951,16.174) AK8(-4.303,16.451) AK18(-9.848,16.266) AK20(-10.801,16.266) AK21(-11.753,16.266) AK60(-36.678,16.523) AK61(-37.328,16.523) AK62(-37.978,16.629) AK63(-38.628,16.629) AL1(0,16.962) AL2(-0.65,16.962) AL3(-1.3,17) AL4(-1.951,17) AL5(-2.901,16.776) AL7(-3.739,16.776) AL8(-4.303,17.101) AL10(-5.658,16.776) AL11(-6.221,17.101) AL13(-7.576,16.776) AL15(-8.14,17.101) AL17(-9.222,16.583) AL18(-9.848,16.916) AL20(-10.801,16.916) AL21(-11.753,16.916) AL22(-12.706,16.916) AL23(-13.529,16.916) AL25(-14.504,16.916) AL26(-15.456,16.916) AL28(-16.409,16.916) AL29(-17.361,16.916) AL31(-18.26,16.591) AL32(-18.824,16.916) AL33(-19.726,16.916) AL35(-20.729,16.916) AL36(-21.58,16.916) AL38(-22.634,16.916) AL39(-23.542,16.591) AL40(-24.131,16.916) AL42(-24.944,16.916) AL43(-25.897,16.916) AL45(-26.874,16.916) AL46(-27.802,16.916) AL48(-28.856,16.916) AL49(-29.757,16.916) AL51(-30.761,16.916) AL52(-31.583,16.916) AL54(-32.61,16.916) AL55(-33.562,16.916) AL57(-34.509,16.916) AL58(-35.408,16.916) AL60(-36.352,17.169) AL61(-37.003,17.169) AM1(0,17.711) AM2(-0.65,17.711) AM3(-1.3,17.673) AM4(-1.951,17.673) AM5(-2.901,17.426) AM7(-3.739,17.426) AM8(-4.303,17.752) AM10(-5.658,17.426) AM11(-6.221,17.752) AM13(-7.576,17.426) AM15(-8.14,17.752) AM17(-9.222,17.233) AM18(-9.848,17.567) AM20(-10.801,17.567) AM21(-11.753,17.567) AM22(-12.706,17.567) AM23(-13.529,17.567) AM25(-14.504,17.567) AM26(-15.456,17.567) AM28(-16.409,17.567) AM29(-17.361,17.567) AM31(-18.26,17.242) AM32(-18.824,17.567) AM33(-19.726,17.567) AM35(-20.729,17.567) AM36(-21.58,17.567) AM38(-22.634,17.567) AM40(-24.131,17.567) AM42(-24.944,17.567) AM43(-25.897,17.567) AM45(-26.874,17.567) AM46(-27.802,17.567) AM48(-28.856,17.567) AM49(-29.757,17.567) AM51(-30.761,17.567) AM52(-31.583,17.567) AM54(-32.61,17.567) AM55(-33.562,17.567) AM57(-34.509,17.567) AM58(-35.408,17.567) AM60(-36.678,17.816) AM61(-37.328,17.816) AM62(-37.978,17.709) AM63(-38.628,17.709) AN1(0,18.46) AN2(-0.65,18.46) AN3(-1.3,18.498) AN4(-1.951,18.498) AN5(-2.901,18.077) AN7(-3.739,18.077) AN8(-4.303,18.402) AN10(-5.658,18.077) AN11(-6.221,18.402) AN13(-7.576,18.077) AN15(-8.14,18.402) AN17(-9.222,17.883) AN18(-9.848,18.217) AN20(-10.801,18.217) AN21(-11.753,18.217) AN22(-12.706,18.217) AN23(-13.529,18.217) AN25(-14.504,18.217) AN26(-15.456,18.217) AN28(-16.409,18.217) AN29(-17.361,18.217) AN31(-18.26,17.892) AN32(-18.824,18.217) AN33(-19.726,18.217) AN35(-20.729,18.217) AN36(-21.58,18.217) AN38(-22.634,18.217) AN39(-23.542,17.892) AN40(-24.131,18.217) AN42(-24.944,18.217) AN43(-25.897,18.217) AN45(-26.874,18.217) AN46(-27.802,18.217) AN48(-28.856,18.217) AN49(-29.757,18.217) AN51(-30.761,18.217) AN52(-31.583,18.217) AN54(-32.61,18.217) AN55(-33.562,18.217) AN57(-34.509,18.217) AN58(-35.408,18.217) AN60(-36.352,18.385) AN61(-37.003,18.385) AN62(-37.653,18.385) AN63(-38.303,18.385) AP1(0,19.21) AP2(-0.65,19.21) AP3(-1.3,19.171) AP4(-1.951,19.171) AP5(-2.901,18.727) AP7(-3.739,18.727) AP8(-4.303,19.052) AP10(-5.658,18.727) AP11(-6.221,19.052) AP13(-7.576,18.727) AP15(-8.14,19.052) AP17(-9.222,18.533) AP18(-9.848,18.867) AP20(-10.801,18.867) AP21(-11.753,18.867) AP22(-12.706,18.867) AP23(-13.529,18.867) AP25(-14.504,18.867) AP26(-15.456,18.867) AP28(-16.409,18.867) AP29(-17.361,18.867) AP31(-18.26,18.542) AP32(-18.824,18.867) AP33(-19.726,18.867) AP35(-20.729,18.867) AP36(-21.58,18.867) AP38(-22.634,18.867) AP39(-23.542,18.542) AP40(-24.131,18.867) AP42(-24.944,18.867) AP43(-25.897,18.867) AP45(-26.874,18.867) AP46(-27.802,18.867) AP48(-28.856,18.867) AP49(-29.757,18.867) AP51(-30.761,18.867) AP52(-31.583,18.867) AP54(-32.61,18.867) AP55(-33.562,18.867) AP57(-34.509,18.867) AP58(-35.408,18.867) AP60(-36.678,19.06) AP61(-37.328,19.06) AP62(-37.978,19.06) AP63(-38.628,19.06) AR5(-2.901,19.377) AR7(-3.739,19.377) AR8(-4.303,19.702) AR10(-5.658,19.377) AR11(-6.221,19.702) AR13(-7.576,19.377) AR15(-8.14,19.702) AR17(-9.222,19.184) AR18(-9.848,19.517) AR20(-10.801,19.517) AR21(-11.753,19.517) AR22(-12.706,19.517) AR23(-13.529,19.517) AR25(-14.504,19.517) AR26(-15.456,19.517) AR28(-16.409,19.517) AR29(-17.361,19.517) AR31(-18.26,19.192) AR32(-18.824,19.517) AR33(-19.726,19.517) AR35(-20.729,19.517) AR36(-21.58,19.517) AR38(-22.634,19.517) AR39(-23.542,19.192) AR40(-24.131,19.517) AR42(-24.944,19.517) AR43(-25.897,19.517) AR45(-26.874,19.517) AR46(-27.802,19.517) AR48(-28.856,19.517) AR49(-29.757,19.517) AR51(-30.761,19.517) AR52(-31.583,19.517) AR54(-32.61,19.517) AR55(-33.562,19.517) AR57(-34.509,19.517) AR58(-35.408,19.517) AT2(-0.65,19.959) AT3(-1.3,19.997) AT4(-1.951,19.997) AT5(-2.901,20.027) AT7(-3.739,20.027) AT10(-5.658,20.027) AT13(-7.576,20.027) AT35(-20.437,20.22) AT37(-22.011,20.22) AT40(-23.586,20.22) AT42(-25.161,20.22) AT43(-26.736,20.22) AT46(-28.311,20.22) AT49(-29.912,20.248) AT61(-37.003,19.634) AT62(-37.812,19.69) AU2(-0.655,20.647) AU3(-1.315,20.647) AU4(-1.976,20.647) AU6(-3.337,20.678) AU7(-4.163,20.678) AU8(-4.836,20.678) AU10(-5.661,20.678) AU11(-6.335,20.678) AU12(-7.16,20.678) AU14(-7.833,20.678) AU15(-8.659,20.678) AU16(-9.222,20.353) AU17(-9.86,20.678) AU18(-10.536,20.353) AU19(-11.105,20.678) AU20(-11.751,20.353) AU21(-12.397,20.678) AU22(-12.966,20.353) AU23(-13.642,20.678) AU24(-14.318,20.353) AU25(-14.993,20.678) AU26(-15.669,20.353) AU27(-16.238,20.678) AU28(-16.884,20.353) AU29(-17.531,20.678) AU30(-18.1,20.353) AU31(-18.775,20.678) AU33(-19.372,20.33) AU34(-19.974,20.678) AU35(-20.899,20.678) AU36(-21.549,20.678) AU37(-22.474,20.678) AU39(-23.124,20.678) AU40(-24.048,20.678) AU41(-24.699,20.678) AU42(-25.623,20.678) AU43(-26.274,20.678) AU44(-27.198,20.678) AU46(-27.848,20.678) AU47(-28.773,20.678) AU49(-29.423,20.678) AU50(-30.4,20.678) AU51(-30.98,20.353) AU52(-31.656,20.678) AU53(-32.331,20.353) AU54(-32.9,20.678) AU55(-33.547,20.353) AU56(-34.193,20.678) AU57(-34.762,20.353) AU58(-35.438,20.678) AU59(-36.002,20.353) AU60(-36.566,20.678) AU61(-37.277,20.401) AU62(-37.978,20.663) AV3(-1.321,21.308) AV4(-1.976,21.308) AV5(-2.664,21.328) AV6(-3.337,21.328) AV7(-4.163,21.328) AV8(-4.836,21.328) AV10(-5.661,21.328) AV11(-6.335,21.328) AV12(-7.16,21.328) AV14(-7.833,21.328) AV15(-8.659,21.328) AV16(-9.222,21.003) AV17(-9.86,21.328) AV18(-10.536,21.003) AV19(-11.105,21.328) AV20(-11.751,21.003) AV21(-12.397,21.328) AV22(-12.966,21.003) AV23(-13.642,21.328) AV24(-14.318,21.003) AV25(-14.993,21.328) AV26(-15.669,21.003) AV27(-16.238,21.328) AV28(-16.884,21.003) AV29(-17.531,21.328) AV30(-18.1,21.003) AV31(-18.775,21.328) AV33(-19.4,21.003) AV34(-20.024,21.328) AV35(-20.849,21.328) AV36(-21.599,21.328) AV37(-22.424,21.328) AV39(-23.173,21.328) AV40(-23.999,21.328) AV41(-24.748,21.328) AV42(-25.574,21.328) AV43(-26.323,21.328) AV44(-27.149,21.328) AV46(-27.898,21.328) AV47(-28.723,21.328) AV49(-29.473,21.328) AV50(-30.298,21.328) AV51(-30.98,21.003) AV52(-31.656,21.328) AV53(-32.331,21.003) AV54(-32.9,21.328) AV55(-33.547,21.003) AV56(-34.193,21.328) AV57(-34.762,21.003) AV58(-35.438,21.328) AV59(-36.002,21.003) AV60(-36.566,21.328) AV61(-37.302,21.051) AW4(-1.976,21.968) AW5(-2.626,21.978) AW6(-3.375,21.978) AW7(-4.125,21.978) AW8(-4.874,21.978) AW10(-5.623,21.978) AW11(-6.373,21.978) AW12(-7.122,21.978) AW14(-7.871,21.978) AW15(-8.621,21.978) AW16(-9.222,21.653) AW17(-9.86,21.978) AW18(-10.536,21.653) AW19(-11.211,21.978) AW21(-12.291,21.978) AW22(-12.966,21.653) AW23(-13.642,21.978) AW24(-14.318,21.653) AW25(-14.993,21.978) AW26(-15.669,21.653) AW27(-16.345,21.978) AW29(-17.424,21.978) AW30(-18.1,21.653) AW31(-18.775,21.978) AW33(-19.451,21.653) AW34(-20.024,21.978) AW35(-20.849,21.978) AW36(-21.599,21.978) AW37(-22.424,21.978) AW39(-23.173,21.978) AW40(-23.999,21.978) AW41(-24.748,21.978) AW42(-25.574,21.978) AW43(-26.323,21.978) AW44(-27.149,21.978) AW46(-27.898,21.978) AW47(-28.723,21.978) AW49(-29.473,21.978) AW50(-30.298,21.978) AW51(-30.98,21.653) AW52(-31.656,21.978) AW53(-32.331,21.653) AW54(-33.007,21.978) AW56(-34.087,21.978) AW57(-34.762,21.653) AW58(-35.438,21.978) AW59(-36.002,21.653) AW60(-36.566,21.978) AY6(-3.375,22.628) AY7(-4.125,22.628) AY8(-4.874,22.628) AY10(-5.623,22.628) AY11(-6.373,22.628) AY12(-7.122,22.628) AY14(-7.871,22.628) AY15(-8.621,22.628) AY16(-9.184,22.303) AY17(-9.86,22.628) AY18(-10.536,22.303) AY19(-11.211,22.628) AY21(-12.291,22.628) AY22(-12.966,22.303) AY23(-13.642,22.628) AY24(-14.318,22.303) AY25(-14.993,22.628) AY26(-15.669,22.303) AY27(-16.345,22.628) AY29(-17.424,22.628) AY30(-18.1,22.303) AY31(-18.775,22.628) AY33(-19.451,22.303) AY34(-20.024,22.628) AY35(-20.849,22.628) AY36(-21.599,22.628) AY37(-22.424,22.628) AY39(-23.173,22.628) AY40(-23.999,22.628) AY41(-24.748,22.628) AY42(-25.574,22.628) AY43(-26.323,22.628) AY44(-27.149,22.628) AY46(-27.898,22.628) AY47(-28.723,22.628) AY49(-29.473,22.628) AY50(-30.298,22.628) AY51(-30.98,22.303) AY52(-31.656,22.628) AY53(-32.331,22.303) AY54(-33.007,22.628) AY56(-34.087,22.628) AY57(-34.762,22.303) AY58(-35.438,22.628) B4(-1.922,0.65) B5(-3.138,0.643) B6(-4.119,0.643) B8(-4.891,0.643) B9(-5.716,0.643) B11(-6.697,0.643) B12(-7.469,0.643) B14(-8.294,0.643) B15(-9.275,0.643) B17(-10.047,0.643) B18(-10.872,0.643) B20(-11.853,0.643) B21(-12.272,1.196) B22(-12.625,0.643) B23(-13.451,0.643) B24(-14.023,0.975) B25(-14.714,0.65) B26(-15.277,0.975) B27(-15.84,0.65) B28(-16.531,0.975) B29(-17.221,0.65) B30(-17.785,0.975) B31(-18.348,0.65) B32(-19.038,0.975) B33(-19.729,0.65) B34(-20.292,0.975) B35(-20.855,0.65) B36(-21.546,0.975) B37(-22.236,0.65) B38(-22.8,0.975) B39(-23.363,0.65) B40(-24.053,0.975) B41(-24.744,0.65) B42(-25.307,0.975) B43(-25.87,0.65) B44(-26.561,0.975) B45(-27.251,0.65) B46(-27.815,0.975) B47(-28.378,0.65) B48(-29.068,0.975) B49(-29.759,0.65) B50(-30.322,0.975) B51(-30.885,0.65) B52(-31.576,0.975) B53(-32.266,0.65) B54(-32.83,0.975) B55(-33.393,0.65) B56(-34.083,0.975) B57(-34.774,0.65) B58(-35.337,0.975) B59(-35.9,0.65) B60(-36.665,0.66) C3(-1.302,1.302) C4(-2.118,1.272) C5(-2.772,1.196) C6(-3.776,1.196) C8(-4.538,1.196) C9(-5.351,1.196) C11(-6.354,1.196) C12(-7.116,1.196) C14(-7.929,1.196) C15(-8.932,1.196) C17(-9.694,1.196) C18(-10.507,1.196) C20(-11.51,1.196) C21(-11.891,1.786) C22(-12.678,1.786) C23(-13.085,1.196) C24(-14.051,2.032) C25(-14.714,1.3) C26(-15.277,1.626) C27(-15.84,1.3) C28(-16.558,2.032) C29(-17.221,1.3) C30(-17.785,1.626) C31(-18.348,1.3) C32(-19.066,2.032) C33(-19.729,1.3) C34(-20.292,1.626) C35(-20.855,1.3) C36(-21.573,2.032) C37(-22.236,1.3) C38(-22.8,1.626) C39(-23.363,1.3) C40(-24.081,2.032) C41(-24.744,1.3) C42(-25.307,1.626) C43(-25.87,1.3) C44(-26.588,2.032) C45(-27.251,1.3) C46(-27.815,1.626) C47(-28.378,1.3) C48(-29.07,2.032) C49(-29.759,1.3) C50(-30.322,1.626) C51(-30.885,1.3) C52(-31.578,1.991) C53(-32.266,1.3) C54(-32.83,1.626) C55(-33.393,1.3) C56(-34.085,1.991) C57(-34.774,1.3) C58(-35.337,1.626) C59(-35.9,1.3) C61(-37.003,1.237) D2(-0.65,2.075) D3(-1.3,2.037) D5(-2.678,1.842) D6(-3.369,1.786) D8(-4.157,1.786) D9(-4.944,1.786) D11(-5.852,1.786) D12(-6.735,1.786) D14(-7.522,1.786) D15(-8.43,1.786) D17(-9.313,1.786) D18(-10.1,1.786) D20(-11.008,1.786) D21(-12.235,2.423) D23(-13.377,1.786) D25(-14.714,1.951) D26(-15.277,2.276) D27(-15.84,1.951) D29(-17.221,1.951) D30(-17.785,2.276) D31(-18.348,1.951) D33(-19.729,1.951) D34(-20.292,2.276) D35(-20.855,1.951) D37(-22.236,1.951) D38(-22.8,2.276) D39(-23.363,1.951) D41(-24.744,1.951) D42(-25.307,2.276) D43(-25.87,1.951) D45(-27.251,1.951) D46(-27.815,2.276) D47(-28.378,1.951) D49(-29.759,1.951) D50(-30.322,2.276) D51(-30.885,1.951) D53(-32.266,1.951) D54(-32.83,2.276) D55(-33.393,1.951) D57(-34.774,1.951) D58(-35.337,2.276) D59(-35.9,1.951) D60(-36.678,1.801) D61(-37.328,1.801) D62(-37.978,2.035) E2(-0.65,2.725) E3(-1.3,2.687) E4(-1.951,2.687) E5(-2.602,2.619) E6(-3.554,2.619) E8(-4.507,2.619) E10(-5.459,2.619) E11(-6.412,2.619) E13(-7.364,2.619) E15(-8.317,2.619) E17(-9.269,2.619) E18(-10.222,2.619) E20(-11.174,2.619) E59(-36.027,2.647) E60(-36.678,2.647) E61(-37.328,2.647) E62(-37.978,2.685) F2(-0.65,3.474) F3(-1.3,3.512) F4(-1.951,3.512) F5(-2.602,3.269) F6(-3.554,3.269) F8(-4.507,3.269) F10(-5.459,3.269) F11(-6.412,3.269) F13(-7.364,3.269) F15(-8.317,3.269) F17(-9.269,3.269) F18(-10.222,3.269) F20(-11.174,3.269) F59(-36.027,3.472) F60(-36.678,3.472) F61(-37.328,3.472) F62(-37.978,3.434) F63(-38.628,3.434) G1(0,4.224) G2(-0.65,4.224) G3(-1.3,4.185) G4(-1.951,4.185) G5(-2.602,3.919) G6(-3.554,3.919) G8(-4.507,3.919) G10(-5.459,3.919) G11(-6.412,3.919) G13(-7.364,3.919) G15(-8.317,3.919) G17(-9.269,3.919) G18(-10.222,3.919) G20(-11.174,3.919) H5(-2.602,4.569) H6(-3.554,4.569) H8(-4.507,4.569) H10(-5.459,4.569) H11(-6.412,4.569) H13(-7.364,4.569) H15(-8.317,4.569) H17(-9.269,4.569) H18(-10.222,4.569) H20(-11.174,4.569) H59(-36.027,4.145) H60(-36.678,4.145) H61(-37.328,4.145) H62(-37.978,4.183) H63(-38.628,4.183) J1(0,4.973) J2(-0.65,4.973) J3(-1.3,5.011) J4(-1.951,5.011) J5(-2.627,5.22) J6(-3.567,5.22) J8(-4.507,5.22) J10(-5.459,5.22) J11(-6.412,5.22) J13(-7.364,5.22) J15(-8.317,5.22) J17(-9.269,5.22) J18(-10.222,5.22) J20(-11.174,5.22) J21(-12.095,4.986) J59(-36.027,4.971) J60(-36.678,4.971) J61(-37.328,4.971) J62(-37.978,4.933) J63(-38.628,4.933) K1(0,5.722) K2(-0.65,5.722) K3(-1.3,5.684) K4(-1.951,5.684) K59(-36.027,5.644) K60(-36.678,5.644) K61(-37.328,5.644) K62(-37.978,5.682) K63(-38.628,5.682) L1(0,6.471) L2(-0.65,6.471) L3(-1.3,6.51) L4(-1.951,6.51) L5(-2.637,6.338) L6(-3.287,6.338) L7(-3.937,6.338) L8(-4.587,6.338) L59(-36.027,6.469) L60(-36.678,6.469) L61(-37.328,6.469) L62(-37.978,6.431) L63(-38.628,6.431) N1(0,7.221) N2(-0.65,7.221) N3(-1.3,7.183) N4(-1.951,7.183) N5(-2.637,7.29) N6(-3.287,7.29) N7(-3.937,7.29) N8(-4.587,7.29) N59(-36.027,7.142) N60(-36.678,7.142) N61(-37.328,7.142) N62(-37.978,7.181) N63(-38.628,7.181) P1(0,7.97) P2(-0.65,7.97) P3(-1.3,8.008) P4(-1.951,8.008) P59(-36.027,7.968) P60(-36.678,7.968) P61(-37.328,7.968) P62(-37.978,7.93) P63(-38.628,7.93) R5(-2.637,8.243) R6(-3.287,8.243) R7(-3.937,8.243) R8(-4.587,8.243) T1(0,8.719) T2(-0.65,8.719) T3(-1.3,8.681) T4(-1.951,8.681) T59(-36.027,8.641) T60(-36.678,8.641) T61(-37.328,8.641) T62(-37.978,8.679) T63(-38.628,8.679) U1(0,9.469) U2(-0.65,9.469) U3(-1.3,9.507) U4(-1.951,9.507) U5(-2.637,9.195) U6(-3.287,9.195) U7(-3.937,9.195) U8(-4.587,9.195) U59(-36.027,9.467) U60(-36.678,9.467) U61(-37.328,9.467) U62(-37.978,9.428) U63(-38.628,9.428) V1(0,10.218) V2(-0.65,10.218) V3(-1.3,10.18) V4(-1.951,10.18) V5(-2.637,10.148) V6(-3.287,10.148) V7(-3.937,10.148) V8(-4.587,10.148) V59(-36.027,10.14) V60(-36.678,10.14) V61(-37.328,10.14) V62(-37.978,10.178) V63(-38.628,10.178) Y1(0,10.967) Y2(-0.65,10.967) Y3(-1.3,11.005) Y4(-1.951,11.005) Y5(-2.637,11.1) Y6(-3.287,11.1) Y7(-3.937,11.1) Y8(-4.587,11.1) Y59(-36.027,10.965) Y60(-36.678,10.965) Y61(-37.328,10.965) Y62(-37.978,10.927) Y63(-38.628,10.927)
  round 0.33 smd: AK22(-12.655,16.266) AK23(-13.529,16.266) AK25(-14.504,16.266) AK26(-15.456,16.266) AK28(-16.409,16.266) AK29(-17.311,16.266) AK32(-18.824,16.266) AK33(-19.726,16.266) AK35(-20.729,16.266) AK36(-21.58,16.266) AK38(-22.609,16.266) AK40(-24.106,16.266) AK42(-24.944,16.266) AK43(-25.897,16.266) AK45(-26.874,16.266) AK46(-27.776,16.266) AK48(-28.83,16.266) AK49(-29.732,16.266) AK51(-30.735,16.266) AK52(-31.583,16.266) AK54(-32.61,16.266) AK55(-33.562,16.266) AK57(-34.509,16.266) AK58(-35.408,16.266)
IDTVMM2320BKG8_BGA_168P-NH
  round 0.279 smd: A1(0,0) A2(0.65,0) A3(1.3,0) A4(1.95,0) A5(2.6,0) A6(3.25,0) A7(3.9,0) A8(4.55,0) A9(5.2,0) A10(5.85,0) A11(6.5,0) A12(7.15,0) A13(7.8,0) A14(8.45,0) B1(0,-0.65) B2(0.65,-0.65) B3(1.3,-0.65) B4(1.95,-0.65) B5(2.6,-0.65) B6(3.25,-0.65) B7(3.9,-0.65) B8(4.55,-0.65) B9(5.2,-0.65) B10(5.85,-0.65) B11(6.5,-0.65) B12(7.15,-0.65) B13(7.8,-0.65) B14(8.45,-0.65) C1(0,-1.3) C2(0.65,-1.3) C3(1.3,-1.3) C4(1.95,-1.3) C5(2.6,-1.3) C6(3.25,-1.3) C7(3.9,-1.3) C8(4.55,-1.3) C9(5.2,-1.3) C10(5.85,-1.3) C11(6.5,-1.3) C12(7.15,-1.3) C13(7.8,-1.3) C14(8.45,-1.3) D1(0,-1.95) D2(0.65,-1.95) D3(1.3,-1.95) D4(1.95,-1.95) D5(2.6,-1.95) D6(3.25,-1.95) D7(3.9,-1.95) D8(4.55,-1.95) D9(5.2,-1.95) D10(5.85,-1.95) D11(6.5,-1.95) D12(7.15,-1.95) D13(7.8,-1.95) D14(8.45,-1.95) E1(0,-2.6) E2(0.65,-2.6) E3(1.3,-2.6) E4(1.95,-2.6) E5(2.6,-2.6) E6(3.25,-2.6) E7(3.9,-2.6) E8(4.55,-2.6) E9(5.2,-2.6) E10(5.85,-2.6) E11(6.5,-2.6) E12(7.15,-2.6) E13(7.8,-2.6) E14(8.45,-2.6) F1(0,-3.25) F2(0.65,-3.25) F3(1.3,-3.25) F4(1.95,-3.25) F5(2.6,-3.25) F6(3.25,-3.25) F7(3.9,-3.25) F8(4.55,-3.25) F9(5.2,-3.25) F10(5.85,-3.25) F11(6.5,-3.25) F12(7.15,-3.25) F13(7.8,-3.25) F14(8.45,-3.25) G1(0,-3.9) G2(0.65,-3.9) G3(1.3,-3.9) G4(1.95,-3.9) G5(2.6,-3.9) G6(3.25,-3.9) G7(3.9,-3.9) G8(4.55,-3.9) G9(5.2,-3.9) G10(5.85,-3.9) G11(6.5,-3.9) G12(7.15,-3.9) G13(7.8,-3.9) G14(8.45,-3.9) H1(0,-4.55) H2(0.65,-4.55) H3(1.3,-4.55) H4(1.95,-4.55) H5(2.6,-4.55) H6(3.25,-4.55) H7(3.9,-4.55) H8(4.55,-4.55) H9(5.2,-4.55) H10(5.85,-4.55) H11(6.5,-4.55) H12(7.15,-4.55) H13(7.8,-4.55) H14(8.45,-4.55) J1(0,-5.2) J2(0.65,-5.2) J3(1.3,-5.2) J4(1.95,-5.2) J5(2.6,-5.2) J6(3.25,-5.2) J7(3.9,-5.2) J8(4.55,-5.2) J9(5.2,-5.2) J10(5.85,-5.2) J11(6.5,-5.2) J12(7.15,-5.2) J13(7.8,-5.2) J14(8.45,-5.2) K1(0,-5.85) K2(0.65,-5.85) K3(1.3,-5.85) K4(1.95,-5.85) K5(2.6,-5.85) K6(3.25,-5.85) K7(3.9,-5.85) K8(4.55,-5.85) K9(5.2,-5.85) K10(5.85,-5.85) K11(6.5,-5.85) K12(7.15,-5.85) K13(7.8,-5.85) K14(8.45,-5.85) L1(0,-6.5) L2(0.65,-6.5) L3(1.3,-6.5) L4(1.95,-6.5) L5(2.6,-6.5) L6(3.25,-6.5) L7(3.9,-6.5) L8(4.55,-6.5) L9(5.2,-6.5) L10(5.85,-6.5) L11(6.5,-6.5) L12(7.15,-6.5) L13(7.8,-6.5) L14(8.45,-6.5) M1(0,-7.15) M2(0.65,-7.15) M3(1.3,-7.15) M4(1.95,-7.15) M5(2.6,-7.15) M6(3.25,-7.15) M7(3.9,-7.15) M8(4.55,-7.15) M9(5.2,-7.15) M10(5.85,-7.15) M11(6.5,-7.15) M12(7.15,-7.15) M13(7.8,-7.15) M14(8.45,-7.15)
